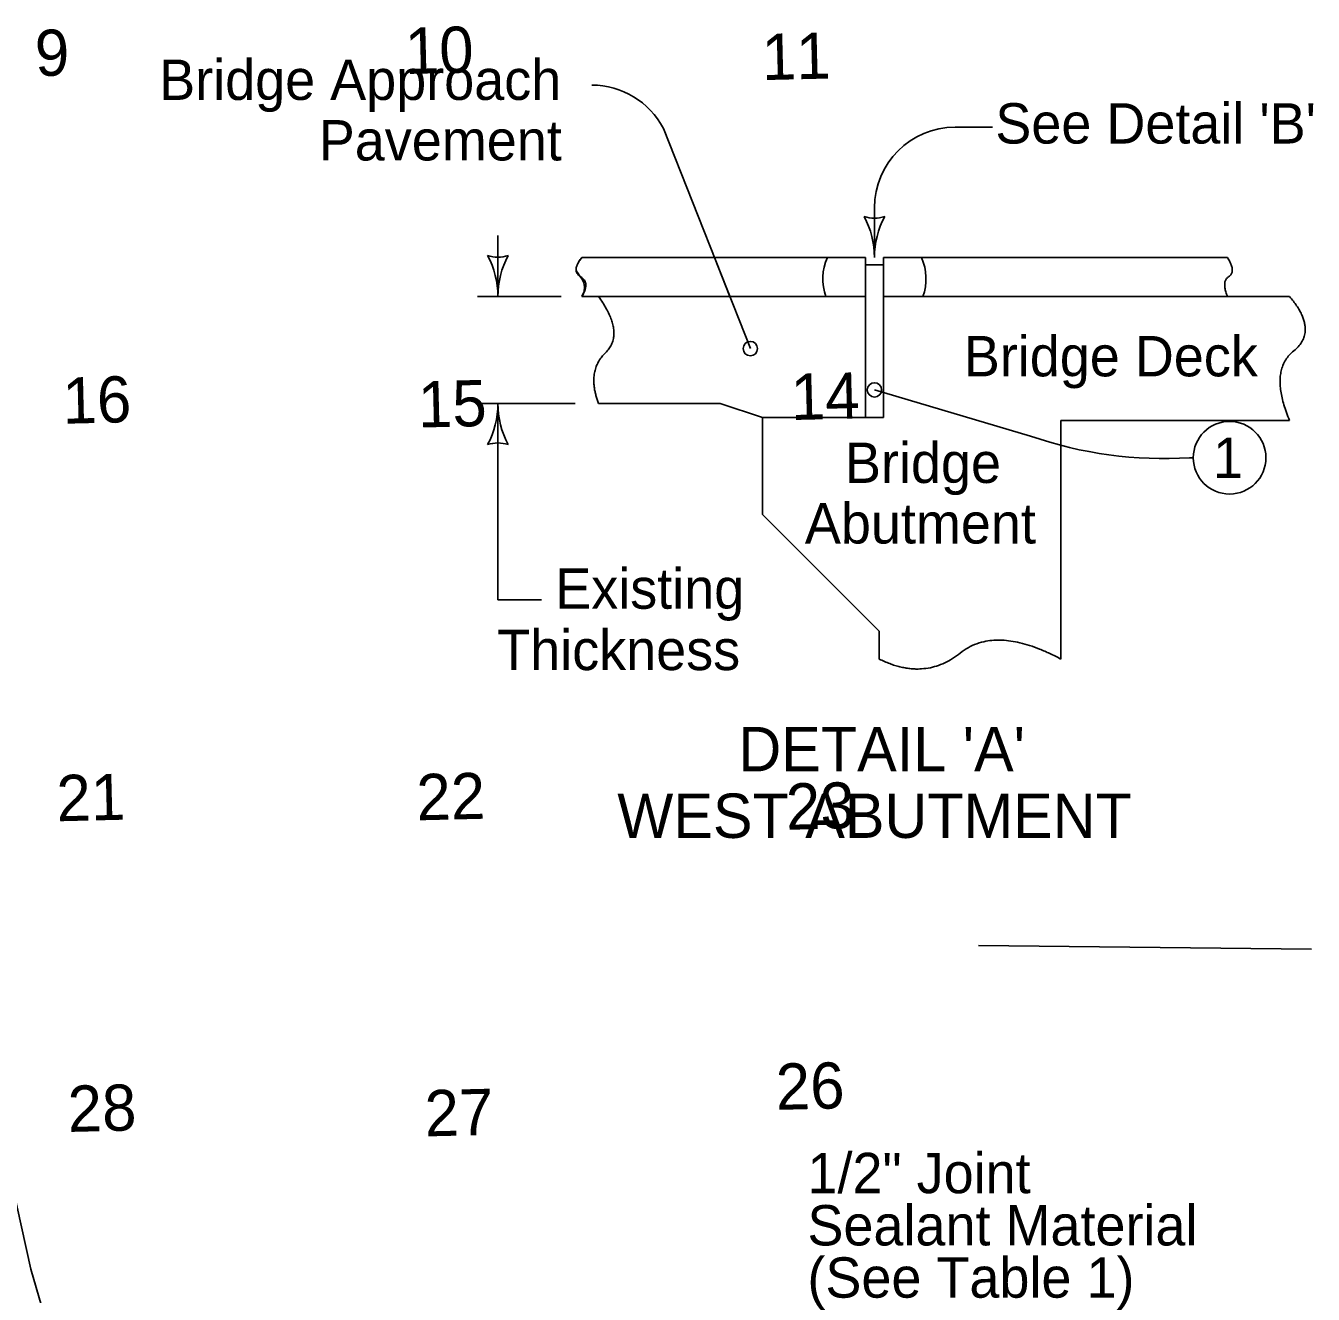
# Model space of a CAD drawing. Extents: x -2933025 to 31692252, y -2344676 to 23854604.
# Drawn here: x -2079935 to -2070365, y -2127236 to -2117809 of the extents above; entities that cross this region are included whole.
import ezdxf

# ---------------------------------------------------------------- set-up
doc = ezdxf.new("R2010")
doc.units = 0
for name, color, linetype in [('Level 2', 7, 'Continuous'), ('Level 3', 7, 'Continuous'), ('tdCoSectLinePart', 7, 'Continuous'), ('tdCoSectNmbr', 7, 'Continuous')]:
    doc.layers.add(name, color=color, linetype=linetype)

msp = doc.modelspace()

# ---------------------------------------------------------------- linework, layer by layer
at = {"layer": 'Level 2'}
for p, q in [((-2074548.5, -2120208), (-2075195.3, -2118571.2)), ((-2073026.5, -2118562.2), (-2072748.8, -2118562.2)), ((-2073626.5, -2119531.4), (-2073626.5, -2119162.2)), ((-2076425.2, -2119367), (-2076425.2, -2119821.2)), ((-2073694, -2119531.4), (-2075801, -2119531.4)), ((-2073694, -2119821.2), (-2073694, -2119531.4)), ((-2073559, -2119585.3), (-2073694, -2119585.3)), ((-2071002.2, -2119531.4), (-2073559, -2119531.4)), ((-2073559, -2119531.4), (-2073559, -2119821.2)), ((-2075953.7, -2119821.2), (-2076576.3, -2119821.2)), ((-2075801, -2119821.2), (-2073694, -2119821.2)), ((-2073694, -2119821.2), (-2073694, -2120721.2)), ((-2073559, -2119821.2), (-2073559, -2120721.2)), ((-2073559, -2119821.2), (-2071002.2, -2119821.2)), ((-2071002.2, -2119821.2), (-2070540.4, -2119821.2)), ((-2072465.4, -2120858.2), (-2073626.1, -2120515)), ((-2075850.6, -2120616.3), (-2076576.3, -2120616.3)), ((-2076425.2, -2120616.3), (-2076425.2, -2122074.8)), ((-2075676.3, -2120616.3), (-2074773.8, -2120616.3)), ((-2074773.8, -2120616.3), (-2074459, -2120721.2)), ((-2073559, -2120721.2), (-2074459, -2120721.2)), ((-2074459, -2120721.2), (-2074459, -2121441.2)), ((-2072241, -2120741.2), (-2072241, -2122515.3)), ((-2072241, -2120741.2), (-2070540.4, -2120741.2)), ((-2071256.3, -2121018.9), (-2071284.8, -2121018.9)), ((-2074459, -2121441.2), (-2073591, -2122308.9)), ((-2076100.1, -2122074.8), (-2076425.2, -2122074.8)), ((-2073591, -2122308.9), (-2073591, -2122515.3))]:
    msp.add_line(p, q, dxfattribs=at)
for centre in [(-2074548.5, -2120208), (-2073626.1, -2120515)]:
    msp.add_circle(centre, 53.3, dxfattribs=at)
for centre, radius, start, end in [((-2075726.9, -2118849.4), 600, 27.61847, 90), ((-2073026.5, -2119162.2), 600, 90, 180), ((-2073626.5, -2118988.4), 250.2, 252.26665, 287.73335), ((-2074274.2, -2119531.4), 647.7, 0, 28.07249), ((-2072978.8, -2119531.4), 647.7, 151.92751, 180), ((-2076425.2, -2119278.2), 250.2, 252.26665, 287.73335), ((-2077072.9, -2119821.2), 647.7, 0, 28.07249), ((-2075777.5, -2119821.2), 647.7, 151.92751, 180), ((-2077072.9, -2120616.3), 647.7, 331.92751, 0), ((-2075777.5, -2120616.3), 647.7, 180, 208.07249), ((-2076425.2, -2121159.4), 250.2, 72.26665, 107.73335), ((-2071478.5, -2118025.2), 3000, 250.79409, 273.70209)]:
    msp.add_arc(centre, radius, start, end, dxfattribs=at)
for points in [[(-2075801, -2119531.4), (-2075882.8, -2119631.9), (-2075738, -2119714.7), (-2075801, -2119821.2)], [(-2071002.2, -2119821.2), (-2071048.5, -2119707.5), (-2070936.2, -2119637.3), (-2071002.2, -2119531.4)], [(-2075676.3, -2119821.2), (-2075479.3, -2120097.7), (-2075769, -2120377.2), (-2075676.3, -2120616.3)], [(-2070540.4, -2119821.2), (-2070324.2, -2120075.2), (-2070696.5, -2120375.6), (-2070540.4, -2120741.2)], [(-2072241, -2122515.3), (-2072723.1, -2122258.1), (-2073253.8, -2122682.9), (-2073591, -2122515.3)]]:
    msp.add_open_spline(points, degree=2, dxfattribs=at)
at = {"layer": 'Level 3'}
for p, q in [((-2075801, -2119531.4), (-2074815.9, -2119531.4)), ((-2074701.3, -2119821.2), (-2074815.9, -2119531.4)), ((-2074815.9, -2119531.4), (-2073976.1, -2119531.4)), ((-2074815.9, -2119531.4), (-2074701.3, -2119821.2)), ((-2073976.1, -2119531.4), (-2073694, -2119531.4)), ((-2073559, -2119531.4), (-2073276.9, -2119531.4)), ((-2073276.9, -2119531.4), (-2071002.2, -2119531.4)), ((-2073694, -2119796.8), (-2073694, -2119821.2)), ((-2073559, -2119821.2), (-2073559, -2119796.9)), ((-2073986.7, -2119821.2), (-2074701.3, -2119821.2)), ((-2073694, -2119821.2), (-2073986.7, -2119821.2)), ((-2073266.3, -2119821.2), (-2073559, -2119821.2)), ((-2071002.2, -2119821.2), (-2073266.3, -2119821.2))]:
    msp.add_line(p, q, dxfattribs=at)
for points in [[(-2073694, -2119531.4), (-2073694, -2119585.3), (-2073694, -2119796.8)], [(-2073559, -2119796.8), (-2073559, -2119585.3), (-2073559, -2119531.4)], [(-2074701.3, -2119821.2), (-2075676.3, -2119821.2), (-2075801, -2119821.2)]]:
    msp.add_lwpolyline(points, dxfattribs=at)
msp.add_circle((-2070986.3, -2121018.9), 270, dxfattribs=at)
for centre, radius, start, end in [((-2075847.9, -2119613), 5.71, 309.4114, 37.06969), ((-2073626.5, -2119689.2), 383.6, 155.70881, 200.1278), ((-2073626.5, -2119689.2), 383.6, 155.70881, 200.1278), ((-2073626.5, -2119689.2), 383.6, 339.8722, 24.29119), ((-2073626.5, -2119689.2), 383.6, 339.8722, 24.29119)]:
    msp.add_arc(centre, radius, start, end, dxfattribs=at)
for start_param, end_param in [(1.570517, 1.570796), (4.71211, 4.712389)]:
    msp.add_ellipse((-2073626.5, -2119796.8), major_axis=(0, 107.6), ratio=0.62744, start_param=start_param, end_param=end_param, dxfattribs=at)
for points, degree in [([(-2075843.3, -2119609.6), (-2075837.6, -2119576.4), (-2075801, -2119531.4)], 2), ([(-2071002.2, -2119531.4), (-2070936.2, -2119637.3), (-2071048.5, -2119707.5), (-2071002.2, -2119821.2)], 2), ([(-2075801, -2119821.2), (-2075738, -2119714.7), (-2075846.4, -2119652.7), (-2075844.3, -2119617.4)], 3)]:
    msp.add_open_spline(points, degree=degree, dxfattribs=at)
at = {"layer": 'tdCoSectLinePart'}
for points in [[(-2072853.3, -2124645.3), (-2070379, -2124671.8)], [(-2078596.3, -2132435.4), (-2078618.5, -2132203.2), (-2078751.4, -2131689), (-2078875.3, -2131087.7), (-2079002.5, -2130438.2), (-2079138, -2129825), (-2079266.5, -2129300.1), (-2079392.8, -2128795.7), (-2079570.2, -2128182.7), (-2079717, -2127671), (-2079896.1, -2127049.4), (-2080036.3, -2126421.2), (-2080122, -2125877.3), (-2080184.5, -2125168.1), (-2080220.8, -2124836.8)]]:
    msp.add_lwpolyline(points, dxfattribs=at)

# ---------------------------------------------------------------- texts
at = {"layer": 'Level 3'}
for s, height, p in [('Bridge Approach ', 300, (-2078942.8, -2118359.8)), ("See Detail 'B'", 300, (-2072727.7, -2118684.1)), ('Pavement', 300, (-2077756.5, -2118809.8)), ('Bridge Deck', 300, (-2072962, -2120414.2)), ('Bridge', 300, (-2073845.1, -2121206.5)), ('1', 300, (-2071109.7, -2121168.9)), ('Abutment', 300, (-2074143.4, -2121656.5)), ('Existing', 300, (-2075998.9, -2122141.5)), ('Thickness', 300, (-2076430.1, -2122597.5)), ("DETAIL 'A'", 330, (-2074637.6, -2123349.6)), ('WEST ABUTMENT', 330, (-2075537.8, -2123844.6)), ('1/2" Joint', 300, (-2074124.3, -2126485.2)), ('Sealant Material', 300, (-2074124.3, -2126873.4)), ('(See Table 1)', 300, (-2074124.3, -2127261.7))]:
    msp.add_text(s, height=height, dxfattribs=at).set_placement(p)
at = {"layer": 'tdCoSectNmbr'}
for s, rotation, p in [('9', 1.38928, (-2079862.3, -2118183.4)), ('10', 1.39009, (-2077112.4, -2118167.4)), ('11', 1.39085, (-2074459.5, -2118212.8)), ('16', 1.38936, (-2079657, -2120766.8)), ('15', 1.39012, (-2077015.5, -2120795.1)), ('14', 1.39092, (-2074243.9, -2120739.2)), ('21', 1.38933, (-2079701.7, -2123721.4)), ('22', 1.3901, (-2077026.2, -2123714.3)), ('23', 1.3909, (-2074280.4, -2123784.5)), ('26', 1.39088, (-2074355.5, -2125866.1)), ('28', 1.38936, (-2079618.7, -2126030.2)), ('27', 1.39013, (-2076965.6, -2126063.4))]:
    msp.add_text(s, height=343.2, rotation=rotation, dxfattribs=at).set_placement(p)

doc.saveas('drawing.dxf')
